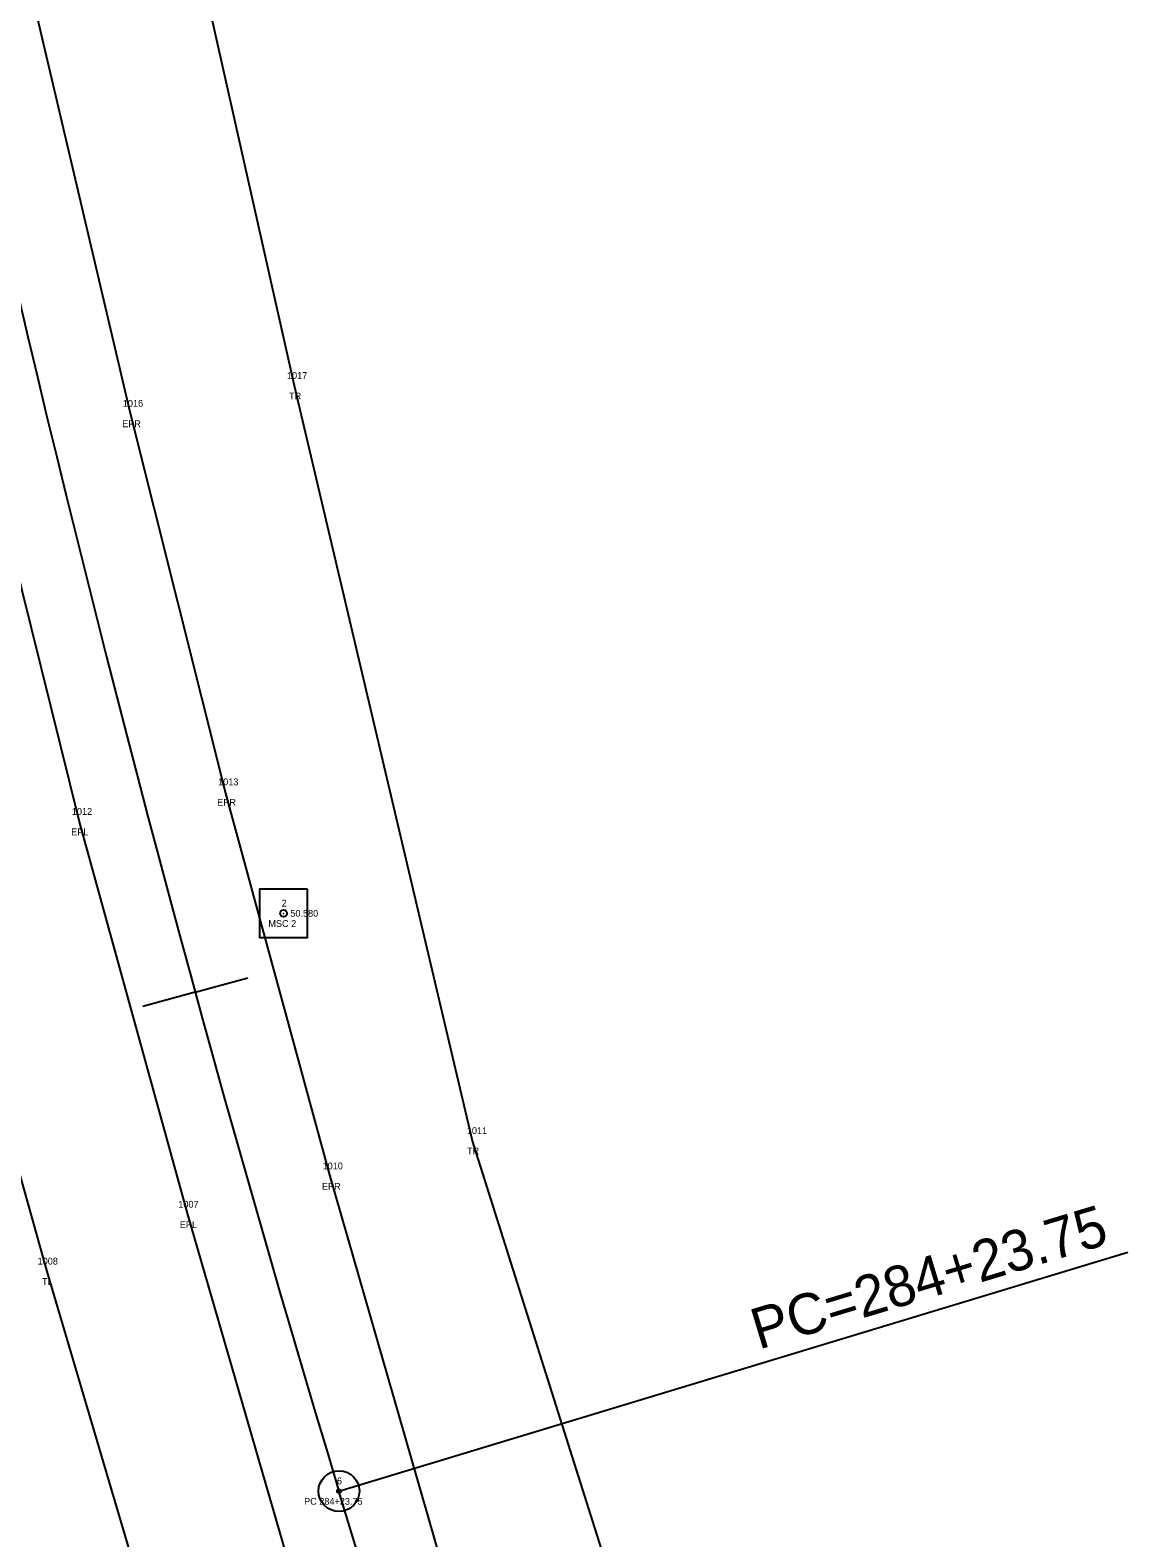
# Model space of a CAD drawing. Extents: x 2445178 to 2446205, y 790762 to 792372.
# Drawn here: x 2445766.2 to 2445927.4, y 791332.4 to 791553.8 of the extents above; entities that cross this region are included whole.
import ezdxf

# ---------------------------------------------------------------- set-up
doc = ezdxf.new("R2010")
doc.units = 0
for name, color, linetype in [('RD_EX_Road', 7, 'Continuous'), ('RD_EX_Road_txCode', 7, 'Continuous'), ('RD_EX_VEG', 7, 'Continuous'), ('RD_EX_VEG_txCode', 7, 'Continuous'), ('RD_HC_Cl', 7, 'Continuous'), ('RD_HC_Data', 7, 'Continuous'), ('RD_HC_Data_Tic', 7, 'Continuous'), ('RD_HC_Survey', 7, 'Continuous'), ('RD_HC_txCode', 7, 'Continuous'), ('RD_SMD_Locator', 7, 'Continuous')]:
    doc.layers.add(name, color=color, linetype=linetype)

msp = doc.modelspace()

# ---------------------------------------------------------------- linework, layer by layer
at = {"layer": 'RD_EX_Road'}
for points in [[(2445850.42, 791174.36), (2445823.13, 791264.7), (2445806.34, 791321.46), (2445789.41, 791379.89), (2445773.46, 791437.57), (2445759.36, 791494.22), (2445744.01, 791559.83), (2445740.09, 791577.64), (2445731.05, 791621.01), (2445722.21, 791669.43), (2445711, 791738.26), (2445706.49, 791765.2), (2445707.32, 791765.82), (2445706.36, 791771.19), (2445705.53, 791771.38), (2445701.96, 791795.92), (2445699.57, 791813.34), (2445693.24, 791870.48), (2445688.14, 791921.92), (2445683.42, 791987.19), (2445680.88, 792033.67), (2445678.74, 792090.55), (2445675.91, 792199.23), (2445673.61, 792301.11)], [(2445870.82, 791182.02), (2445844.02, 791271.27), (2445827.31, 791326.39), (2445810.32, 791385.52), (2445794.94, 791441.92), (2445780.98, 791497.5), (2445766.72, 791558.1)]]:
    msp.add_lwpolyline(points, dxfattribs=at)
at = {"layer": 'RD_EX_VEG'}
for points in [[(2445895.98, 791185.85), (2445831.19, 791390.71), (2445805.05, 791501.58), (2445775.97, 791631.01), (2445748.83, 791769.92)], [(2445828.32, 791169.91), (2445768.75, 791371.54), (2445736.16, 791487.68), (2445726.82, 791546.26), (2445672.34, 791533.07)]]:
    msp.add_lwpolyline(points, dxfattribs=at)
at = {"layer": 'RD_HC_Cl'}
msp.add_line((2445860.1, 791179.04), (2445811.59, 791339.27), dxfattribs=at)
msp.add_arc((2448553.48, 792169.37), 2864.79, 181.3527, 196.84356, dxfattribs=at)
at = {"layer": 'RD_HC_Data'}
msp.add_line((2445811.59, 791339.27), (2445927.45, 791374.34), dxfattribs=at)
for radius in [3, 0.282]:
    msp.add_circle((2445811.59, 791339.27), radius, dxfattribs=at)
at = {"layer": 'RD_HC_Data_Tic'}
for q in [(2445798.19, 791414.64), (2445782.76, 791410.41)]:
    msp.add_line((2445790.48, 791412.53), q, dxfattribs=at)
at = {"layer": 'RD_HC_Survey'}
msp.add_lwpolyline([(2445806.99, 791427.64), (2445799.92, 791427.64), (2445799.92, 791420.57), (2445806.99, 791420.57)], close=True, dxfattribs=at)
msp.add_circle((2445803.45, 791424.11), 0.5, dxfattribs=at)
at = {"layer": 'RD_SMD_Locator'}
for centre in [(2445805.05, 791501.58), (2445780.98, 791497.5), (2445794.94, 791441.92), (2445773.46, 791437.57), (2445803.45, 791424.11), (2445831.19, 791390.71), (2445810.32, 791385.52), (2445789.41, 791379.89), (2445768.75, 791371.54), (2445811.59, 791339.27)]:
    msp.add_circle(centre, 0.001, dxfattribs=at)

# ---------------------------------------------------------------- texts
at = {"layer": 'RD_EX_Road_txCode'}
for s, p in [('1016', (2445779.85, 791498.5)), ('EPR', (2445779.75, 791495.5)), ('1013', (2445793.84, 791442.92)), ('EPR', (2445793.71, 791439.92)), ('1012', (2445772.36, 791438.57)), ('EPL', (2445772.26, 791435.57)), ('50.580', (2445804.45, 791423.61)), ('1010', (2445809.18, 791386.52)), ('EPR', (2445809.09, 791383.52)), ('1007', (2445787.99, 791380.89)), ('EPL', (2445788.21, 791377.89))]:
    msp.add_text(s, height=1, dxfattribs=at).set_placement(p)
at = {"layer": 'RD_EX_VEG_txCode'}
for s, p in [('1017', (2445803.95, 791502.58)), ('TR', (2445804.26, 791499.58)), ('1011', (2445830.37, 791391.71)), ('TR', (2445830.4, 791388.71)), ('1008', (2445767.33, 791372.54)), ('TL', (2445767.98, 791369.54))]:
    msp.add_text(s, height=1, dxfattribs=at).set_placement(p)
at = {"layer": 'RD_HC_Data'}
msp.add_text('PC=284+23.75', height=6, rotation=16.8436, dxfattribs=at).set_placement((2445873.23, 791360.02))
at = {"layer": 'RD_HC_txCode'}
for s, p in [('2', (2445803.17, 791425.11)), ('MSC 2', (2445801.22, 791422.11)), ('6', (2445811.29, 791340.27)), ('PC 284+23.75', (2445806.47, 791337.27))]:
    msp.add_text(s, height=1, dxfattribs=at).set_placement(p)

doc.saveas('drawing.dxf')
